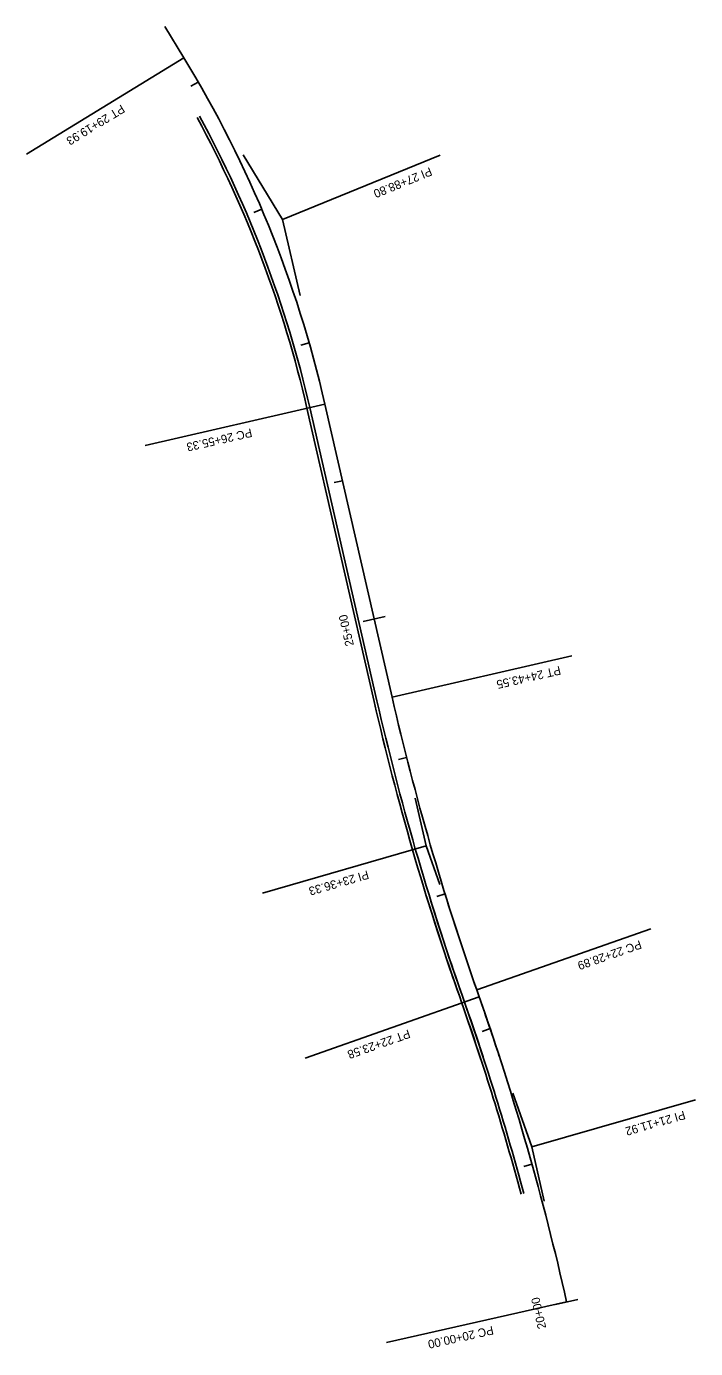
# Model space of a CAD drawing. Extents: x 955367 to 987800, y 1869413 to 1923417.
# Drawn here: x 957608 to 958080, y 1919040 to 1919971 of the extents above; entities that cross this region are included whole.
import ezdxf

# ---------------------------------------------------------------- set-up
doc = ezdxf.new("R2010")
doc.units = 0
for name, color, linetype in [('R_Horz Alg', 7, 'Continuous'), ('R_Horz Alg Annot', 7, 'Continuous'), ('R_Proposed Road', 7, 'Continuous')]:
    doc.layers.add(name, color=color, linetype=linetype)

msp = doc.modelspace()

# ---------------------------------------------------------------- linework, layer by layer
at = {"layer": 'R_Horz Alg'}
for p, q in [((957719.29, 1919948.69), (957705.82, 1919970.74)), ((957866.07, 1919498.31), (957818.74, 1919704.73)), ((957927.46, 1919287.21), (957925.7, 1919292.21)), ((957927.46, 1919287.21), (957925.7, 1919292.21))]:
    msp.add_line(p, q, dxfattribs=at)
for centre, radius, start, end in [((957020.93, 1919521.78), 818.51, 12.91576, 31.43797), ((959727.61, 1919925.2), 1909.86, 192.91576, 199.35559), ((959727.61, 1919925.2), 1909.86, 197.20683, 199.35559), ((956125.54, 1918654.22), 1909.86, 12.64806, 19.35559), ((956125.54, 1918654.22), 1909.86, 18.03426, 19.35559)]:
    msp.add_arc(centre, radius, start, end, dxfattribs=at)
at = {"layer": 'R_Horz Alg Annot'}
for p, q in [((957788.9, 1919834.82), (957761.09, 1919880.32)), ((957788.9, 1919834.82), (957761.09, 1919880.32)), ((957801.19, 1919781.26), (957788.9, 1919834.82)), ((957801.19, 1919781.26), (957788.9, 1919834.82)), ((957882.37, 1919427.24), (957890.09, 1919393.58)), ((957899.62, 1919366.45), (957890.09, 1919393.58)), ((957964.55, 1919181.61), (957951.24, 1919219.5)), ((957973.12, 1919143.42), (957964.55, 1919181.61))]:
    msp.add_line(p, q, dxfattribs=at)
for points in [[(957719.29, 1919948.69), (957608.37, 1919880.89)], [(957724.29, 1919928.56), (957729.48, 1919931.56)], [(957788.9, 1919834.82), (957900.03, 1919880.11)], [(957768.62, 1919839.81), (957774.14, 1919842.15)], [(957801.8, 1919746.32), (957807.57, 1919747.97)], [(957818.74, 1919704.73), (957692.02, 1919675.67)], [(957825.25, 1919649.46), (957831.1, 1919650.8)], [(957845.66, 1919551.54), (957861.25, 1919555.12)], [(957866.07, 1919498.31), (957992.78, 1919527.36)], [(957870.47, 1919454.5), (957876.29, 1919455.97)], [(957890.09, 1919393.58), (957774.81, 1919360.23)], [(957897.65, 1919357.95), (957903.38, 1919359.73)], [(957897.65, 1919357.95), (957903.38, 1919359.73)], [(957925.7, 1919292.21), (958048.35, 1919335.3)], [(957925.7, 1919292.21), (958048.35, 1919335.3)], [(957927.46, 1919287.21), (957804.8, 1919244.12)], [(957927.46, 1919287.21), (957804.8, 1919244.12)], [(957929.45, 1919262.99), (957935.14, 1919264.91)], [(957929.45, 1919262.99), (957935.14, 1919264.91)], [(957964.55, 1919181.61), (958079.9, 1919214.69)], [(957958.84, 1919167.74), (957964.62, 1919169.36)], [(957989.06, 1919072.41), (957862.21, 1919043.94)], [(957981.25, 1919070.66), (957996.86, 1919074.16)]]:
    msp.add_lwpolyline(points, dxfattribs=at)
at = {"layer": 'R_Proposed Road'}
for p, q in [((957855.35, 1919495.85), (957808.01, 1919702.27)), ((957853.4, 1919495.4), (957806.06, 1919701.82)), ((957915.19, 1919282.9), (957913.43, 1919287.9)), ((957915.19, 1919282.9), (957913.43, 1919287.9)), ((957917.08, 1919283.56), (957915.32, 1919288.57)), ((957917.08, 1919283.56), (957915.32, 1919288.57))]:
    msp.add_line(p, q, dxfattribs=at)
for centre, radius, start, end in [((957020.93, 1919521.78), 807.51, 12.91576, 28.53259), ((957020.93, 1919521.78), 805.51, 12.91576, 28.53259), ((959727.61, 1919925.2), 1922.86, 192.91576, 199.35559), ((959727.61, 1919925.2), 1920.86, 192.91576, 199.35559), ((959727.61, 1919925.2), 1922.86, 197.15785, 199.35559), ((959727.61, 1919925.2), 1920.86, 197.16535, 199.35559), ((956125.54, 1918654.22), 1898.86, 15.09821, 19.35559), ((956125.54, 1918654.22), 1898.86, 17.95478, 19.35559), ((956125.54, 1918654.22), 1896.86, 15.1008, 19.35559), ((956125.54, 1918654.22), 1896.86, 17.94023, 19.35559)]:
    msp.add_arc(centre, radius, start, end, dxfattribs=at)

# ---------------------------------------------------------------- texts
at = {"layer": 'R_Horz Alg Annot'}
for s, rotation, p in [('PT 29+19.93', 211.43797, (957675.29, 1919915.93)), ('PI 27+88.80', 202.17687, (957892.65, 1919871.71)), ('PC 26+55.33', 192.91576, (957766.61, 1919687.65)), ('25+00', 102.91576, (957839.18, 1919535.03)), ('PT 24+43.55', 192.91576, (957984.15, 1919520.26)), ('PI 23+36.33', 196.13568, (957848.61, 1919376.38)), ('PC 22+28.89', 199.35559, (958040.57, 1919327.27)), ('PC 22+28.89', 199.35559, (958040.57, 1919327.27)), ('PT 22+23.58', 199.35559, (957877.55, 1919264.37)), ('PT 22+23.58', 199.35559, (957877.55, 1919264.37)), ('PI 21+11.92', 196.00182, (958071.67, 1919207.13)), ('20+00', 102.64806, (957974.7, 1919054.18)), ('PC 20+00.00', 192.64806, (957936.77, 1919055.55))]:
    msp.add_text(s, height=6, rotation=rotation, dxfattribs=at).set_placement(p)

doc.saveas('drawing.dxf')
